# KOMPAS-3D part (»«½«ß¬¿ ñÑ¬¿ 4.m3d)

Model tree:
1. Эскиз:1
2. Операция выдавливания:1
     Толщина стенки 1 = 2.3; Толщина стенки 2 = 2.3; Расстояние 1 = 0.6; Расстояние 2 = 0.6
3. Эскиз:2
4. Операция выдавливания:2
     Толщина стенки 1 = 2.3; Толщина стенки 2 = 2.3; Расстояние 1 = 0.6; Расстояние 2 = 0.6
5. Эскиз:3
6. Вырезать элемент выдавливания:1
     Толщина стенки 1 = 3; Толщина стенки 2 = 3; Расстояние 1 = 10
7. Эскиз:4
8. Вырезать элемент выдавливания:2
     Толщина стенки 1 = 3; Толщина стенки 2 = 3; Расстояние 1 = 10
9. Вырезать элемент выдавливания:3
     Расстояние 1 = 10
